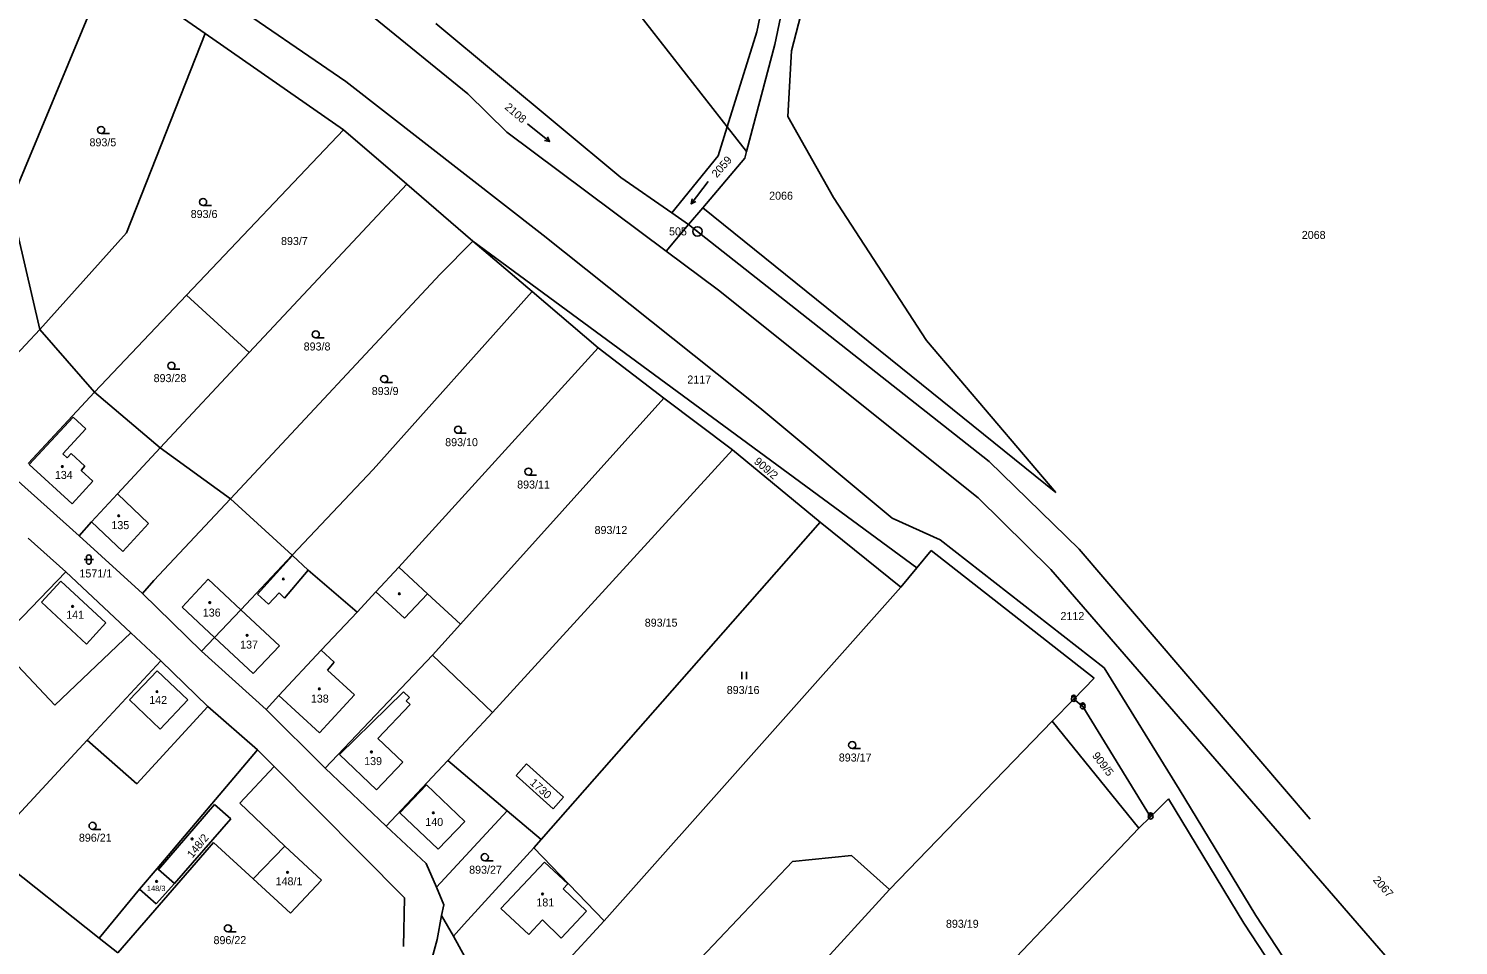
# Model space of a CAD drawing. Extents: x -801826 to -800592, y -1032871 to -1031813.
# Drawn here: x -800902.2 to -800598.5, y -1032747.9 to -1032553.2 of the extents above; entities that cross this region are included whole.
import ezdxf

# ---------------------------------------------------------------- set-up
doc = ezdxf.new("R2010")
doc.units = 0
for name, color, linetype in [('Vrstva 1', 7, 'Continuous'), ('Vrstva 17', 7, 'Continuous'), ('Vrstva 18', 7, 'Continuous'), ('Vrstva 19', 7, 'Continuous'), ('Vrstva 24', 7, 'Continuous'), ('Vrstva 25', 7, 'Continuous'), ('Vrstva 4', 7, 'Continuous')]:
    doc.layers.add(name, color=color, linetype=linetype)

msp = doc.modelspace()

# ---------------------------------------------------------------- linework, layer by layer
at = {"layer": 'Vrstva 1'}
for p, q in [((-800747.51, -1032553.85), (-800720.4, -1032423.37)), ((-800743.69, -1032556.55), (-800734.56, -1032513.71)), ((-800795.04, -1032521.25), (-800753.78, -1032574.05)), ((-800740.12, -1032557.88), (-800734.46, -1032535.8)), ((-800906.01, -1032590.17), (-800885.17, -1032539.97)), ((-800884.24, -1032540.59), (-800864.66, -1032554.23)), ((-800834.81, -1032564.44), (-800862.95, -1032545.07)), ((-800828.93, -1032550.72), (-800808.91, -1032567.02)), ((-800815.65, -1032552.08), (-800776.4, -1032584.81)), ((-800881.38, -1032596.58), (-800864.66, -1032554.23)), ((-800864.66, -1032554.23), (-800835.29, -1032574.68)), ((-800753.78, -1032574.05), (-800747.51, -1032553.85)), ((-800749.69, -1032579.25), (-800743.69, -1032556.55)), ((-800740.88, -1032571.84), (-800740.12, -1032557.88)), ((-800792.86, -1032597.07), (-800834.81, -1032564.44)), ((-800808.91, -1032567.02), (-800800.57, -1032575.14)), ((-800755.69, -1032580.22), (-800753.78, -1032574.05)), ((-800753.78, -1032574.05), (-800749.69, -1032579.25)), ((-800731.22, -1032589.07), (-800740.88, -1032571.84)), ((-800868.63, -1032609.77), (-800835.29, -1032574.68)), ((-800821.82, -1032586.21), (-800835.29, -1032574.68)), ((-800766.77, -1032600.41), (-800800.57, -1032575.14)), ((-800765.55, -1032592.3), (-800755.69, -1032580.22)), ((-800750.07, -1032580.68), (-800749.69, -1032579.25)), ((-800758.99, -1032591.22), (-800750.07, -1032580.68)), ((-800855.31, -1032621.97), (-800821.82, -1032586.21)), ((-800807.81, -1032598.33), (-800821.82, -1032586.21)), ((-800776.4, -1032584.81), (-800765.55, -1032592.3)), ((-800711.46, -1032619.4), (-800731.22, -1032589.07)), ((-800899.82, -1032617.08), (-800906.01, -1032590.17)), ((-800765.55, -1032592.3), (-800761.99, -1032594.76)), ((-800761.99, -1032594.76), (-800758.99, -1032591.22)), ((-800758.99, -1032591.22), (-800684, -1032651.66)), ((-800761.99, -1032594.76), (-800766.77, -1032600.41)), ((-800698.17, -1032645.09), (-800761.99, -1032594.76)), ((-800899.82, -1032617.08), (-800881.38, -1032596.58)), ((-800814.78, -1032605.32), (-800807.81, -1032598.33)), ((-800713.51, -1032667.66), (-800807.81, -1032598.33)), ((-800795.21, -1032609.02), (-800807.81, -1032598.33)), ((-800746.85, -1032633.68), (-800792.86, -1032597.07)), ((-800755.66, -1032608.71), (-800766.77, -1032600.41)), ((-800859.27, -1032653.03), (-800814.78, -1032605.32)), ((-800888.19, -1032630.36), (-800868.63, -1032609.77)), ((-800868.63, -1032609.77), (-800855.31, -1032621.97)), ((-800829.01, -1032646.84), (-800795.21, -1032609.02)), ((-800781.17, -1032620.96), (-800795.21, -1032609.02)), ((-800755.66, -1032608.71), (-800700.48, -1032652.79)), ((-800899.82, -1032617.08), (-800910.98, -1032628.99)), ((-800888.19, -1032630.36), (-800899.82, -1032617.08)), ((-800684, -1032651.66), (-800711.46, -1032619.4)), ((-800874.26, -1032642.21), (-800855.31, -1032621.97)), ((-800823.54, -1032667.55), (-800781.17, -1032620.96)), ((-800781.17, -1032620.96), (-800767.24, -1032631.65)), ((-800902.29, -1032645.52), (-800888.19, -1032630.36)), ((-800874.26, -1032642.21), (-800888.19, -1032630.36)), ((-800810.46, -1032679.66), (-800767.24, -1032631.65)), ((-800767.24, -1032631.65), (-800752.63, -1032642.64)), ((-800718.76, -1032657.14), (-800746.85, -1032633.68)), ((-800883.28, -1032651.94), (-800874.26, -1032642.21)), ((-800874.26, -1032642.21), (-800859.27, -1032653.03)), ((-800752.63, -1032642.64), (-800803.67, -1032698.44)), ((-800734.01, -1032657.96), (-800752.63, -1032642.64)), ((-800846.17, -1032664.97), (-800829.01, -1032646.84)), ((-800679.03, -1032663.74), (-800698.17, -1032645.09)), ((-800891.41, -1032660.9), (-800905.05, -1032648.69)), ((-800888.84, -1032657.94), (-800883.28, -1032651.94)), ((-800875.6, -1032670.39), (-800859.27, -1032653.03)), ((-800846.17, -1032664.97), (-800859.27, -1032653.03)), ((-800700.48, -1032652.79), (-800685.05, -1032668.07)), ((-800891.41, -1032660.9), (-800888.84, -1032657.94)), ((-800793.3, -1032725.41), (-800734.01, -1032657.96)), ((-800734.01, -1032657.96), (-800716.93, -1032671.82)), ((-800708.57, -1032661.74), (-800718.76, -1032657.14)), ((-800894.26, -1032668.56), (-800902.29, -1032661.37)), ((-800877.98, -1032673.15), (-800891.41, -1032660.9)), ((-800673.72, -1032688.93), (-800708.57, -1032661.74)), ((-800857.07, -1032676.61), (-800846.17, -1032664.97)), ((-800846.09, -1032665.04), (-800846.17, -1032664.97)), ((-800842.77, -1032668.15), (-800846.09, -1032665.04)), ((-800710.49, -1032664.04), (-800713.51, -1032667.66)), ((-800675.83, -1032691.09), (-800710.49, -1032664.04)), ((-800629.94, -1032721.03), (-800679.03, -1032663.74)), ((-800908.97, -1032683.75), (-800894.26, -1032668.56)), ((-800880.44, -1032681.5), (-800894.26, -1032668.56)), ((-800832.41, -1032677.07), (-800842.77, -1032668.15)), ((-800828.41, -1032672.79), (-800823.54, -1032667.55)), ((-800823.54, -1032667.55), (-800817.45, -1032673.19)), ((-800713.51, -1032667.66), (-800716.93, -1032671.82)), ((-800685.05, -1032668.07), (-800610.32, -1032754.24)), ((-800877.98, -1032673.15), (-800875.6, -1032670.39)), ((-800865.46, -1032685.41), (-800877.98, -1032673.15)), ((-800832.41, -1032677.07), (-800828.41, -1032672.79)), ((-800817.45, -1032673.19), (-800810.46, -1032679.66)), ((-800716.93, -1032671.82), (-800779.9, -1032742.67)), ((-800862.68, -1032682.47), (-800857.07, -1032676.61)), ((-800840.04, -1032685.14), (-800832.41, -1032677.07)), ((-800816.36, -1032686.22), (-800810.46, -1032679.66)), ((-800908.97, -1032683.75), (-800896.63, -1032696.82)), ((-800896.63, -1032696.82), (-800880.44, -1032681.5)), ((-800874.12, -1032687.42), (-800880.44, -1032681.5)), ((-800865.46, -1032685.41), (-800862.68, -1032682.47)), ((-800851.7, -1032697.76), (-800865.46, -1032685.41)), ((-800849.02, -1032694.81), (-800840.04, -1032685.14)), ((-800839.18, -1032710.22), (-800816.36, -1032686.22)), ((-800816.36, -1032686.22), (-800803.67, -1032698.44)), ((-800889.71, -1032704.26), (-800874.12, -1032687.42)), ((-800864.1, -1032697.13), (-800874.12, -1032687.42)), ((-800657.77, -1032714.7), (-800673.72, -1032688.93)), ((-800680.18, -1032695.55), (-800675.83, -1032691.09)), ((-800851.7, -1032697.76), (-800849.02, -1032694.81)), ((-800684.75, -1032700.23), (-800680.18, -1032695.55)), ((-800678.26, -1032697.15), (-800680.18, -1032695.55)), ((-800864.1, -1032697.13), (-800879.2, -1032713.56)), ((-800853.56, -1032706.35), (-800864.1, -1032697.13)), ((-800839.18, -1032710.22), (-800851.7, -1032697.76)), ((-800803.67, -1032698.44), (-800813.1, -1032708.63)), ((-800663.84, -1032720.54), (-800678.26, -1032697.15)), ((-800719.34, -1032735.97), (-800684.75, -1032700.23)), ((-800666.33, -1032723), (-800684.75, -1032700.23)), ((-800911.15, -1032727.37), (-800889.71, -1032704.26)), ((-800879.2, -1032713.56), (-800889.71, -1032704.26)), ((-800874.85, -1032731.51), (-800853.56, -1032706.35)), ((-800850.03, -1032709.9), (-800853.56, -1032706.35)), ((-800857.32, -1032717.69), (-800850.03, -1032709.9)), ((-800850.03, -1032709.9), (-800822.34, -1032737.75)), ((-800826.26, -1032722.56), (-800839.18, -1032710.22)), ((-800813.1, -1032708.63), (-800826.26, -1032722.56)), ((-800813.1, -1032708.63), (-800800.53, -1032719.29)), ((-800798.61, -1032711.8), (-800796.41, -1032709.34)), ((-800796.41, -1032709.34), (-800788.55, -1032716.38)), ((-800790.75, -1032718.84), (-800798.61, -1032711.8)), ((-800788.55, -1032716.38), (-800790.75, -1032718.84)), ((-800660.02, -1032716.77), (-800663.84, -1032720.54)), ((-800644.04, -1032743.12), (-800660.02, -1032716.77)), ((-800641.5, -1032741.52), (-800657.77, -1032714.7)), ((-800874.61, -1032731.74), (-800862.71, -1032717.98)), ((-800862.71, -1032717.98), (-800859.24, -1032721.02)), ((-800847.74, -1032726.79), (-800857.32, -1032717.69)), ((-800800.53, -1032719.29), (-800815.57, -1032735.5)), ((-800800.53, -1032719.29), (-800793.3, -1032725.41)), ((-800859.24, -1032721.02), (-800871.19, -1032734.75)), ((-800826.26, -1032722.56), (-800817.71, -1032730.51)), ((-800704.52, -1032763.01), (-800666.33, -1032723)), ((-800666.33, -1032723), (-800663.84, -1032720.54)), ((-800862.89, -1032726), (-800883.21, -1032749.46)), ((-800854.49, -1032733.72), (-800862.89, -1032726)), ((-800794.87, -1032727.17), (-800793.3, -1032725.41)), ((-800887.16, -1032746.32), (-800911.15, -1032727.37)), ((-800839.99, -1032734.05), (-800847.74, -1032726.79)), ((-800794.87, -1032727.17), (-800809.66, -1032743.38)), ((-800794.87, -1032727.17), (-800779.9, -1032742.67)), ((-800727.36, -1032728.75), (-800739.93, -1032730.06)), ((-800719.34, -1032735.97), (-800727.36, -1032728.75)), ((-800878.59, -1032735.91), (-800874.85, -1032731.51)), ((-800874.85, -1032731.51), (-800874.61, -1032731.74)), ((-800874.61, -1032731.74), (-800871.19, -1032734.75)), ((-800817.71, -1032730.51), (-800815.57, -1032735.5)), ((-800792.6, -1032730.18), (-800801.86, -1032740.03)), ((-800787.64, -1032734.82), (-800792.6, -1032730.18)), ((-800775.49, -1032767.53), (-800739.93, -1032730.06)), ((-800871.19, -1032734.75), (-800875.08, -1032739.04)), ((-800846.53, -1032741.02), (-800854.49, -1032733.72)), ((-800846.53, -1032741.02), (-800839.99, -1032734.05)), ((-800788.6, -1032735.85), (-800787.64, -1032734.82)), ((-800887.16, -1032746.32), (-800878.59, -1032735.91)), ((-800875.08, -1032739.04), (-800878.59, -1032735.91)), ((-800822.52, -1032748.12), (-800822.34, -1032737.75)), ((-800815.57, -1032735.5), (-800813.95, -1032739.28)), ((-800783.65, -1032740.59), (-800788.6, -1032735.85)), ((-800719.34, -1032735.97), (-800755.52, -1032775.59)), ((-800815.39, -1032746.59), (-800814.46, -1032741.51)), ((-800813.95, -1032739.28), (-800814.46, -1032741.51)), ((-800814.46, -1032741.51), (-800811.93, -1032745.91)), ((-800801.86, -1032740.03), (-800795.94, -1032745.59)), ((-800789.09, -1032746.32), (-800783.65, -1032740.59)), ((-800598.47, -1032807.13), (-800641.5, -1032741.52)), ((-800811.93, -1032745.91), (-800809.66, -1032743.38)), ((-800795.94, -1032745.59), (-800793.01, -1032742.47)), ((-800793.01, -1032742.47), (-800789.09, -1032746.32)), ((-800779.9, -1032742.67), (-800788.9, -1032752.39)), ((-800600.58, -1032809.38), (-800644.04, -1032743.12)), ((-800883.21, -1032749.46), (-800887.16, -1032746.32)), ((-800816.49, -1032750.53), (-800815.39, -1032746.59)), ((-800801.15, -1032765.61), (-800811.93, -1032745.91))]:
    msp.add_line(p, q, dxfattribs=at)
at = {"layer": 'Vrstva 24'}
for centre, radius in [((-800760.12, -1032596.24), 1), ((-800760.12, -1032596.24), 0.0439), ((-800680.18, -1032695.55), 0.5), ((-800680.18, -1032695.55), 0.0364), ((-800678.26, -1032697.15), 0.5), ((-800678.26, -1032697.15), 0.0364), ((-800663.84, -1032720.54), 0.5), ((-800663.84, -1032720.54), 0.0364)]:
    msp.add_circle(centre, radius, dxfattribs=at)
for centre in [(-800680.18, -1032695.18), (-800678.26, -1032696.78), (-800663.84, -1032720.17)]:
    msp.add_arc(centre, 0.45, 344.4473, 196.3778, dxfattribs=at)
at = {"layer": 'Vrstva 25'}
for p, q in [((-800796.19, -1032573.38), (-800791.53, -1032577.14)), ((-800885.03, -1032575.44), (-800886.78, -1032575.44)), ((-800757.81, -1032585.63), (-800761.43, -1032590.41)), ((-800863.36, -1032590.75), (-800865.11, -1032590.75)), ((-800839.43, -1032618.86), (-800841.18, -1032618.86)), ((-800870.09, -1032625.53), (-800871.84, -1032625.53)), ((-800824.9, -1032628.35), (-800826.65, -1032628.35)), ((-800809.21, -1032639.12), (-800810.96, -1032639.12)), ((-800794.27, -1032648), (-800796.02, -1032648)), ((-800889.9, -1032666.43), (-800889.9, -1032665.43)), ((-800888.9, -1032666.43), (-800888.9, -1032665.43)), ((-800890.4, -1032665.93), (-800888.4, -1032665.93)), ((-800750.71, -1032689.8), (-800750.71, -1032691.3)), ((-800749.69, -1032691.3), (-800749.69, -1032689.8)), ((-800725.49, -1032706.08), (-800727.24, -1032706.08)), ((-800886.84, -1032723.23), (-800888.59, -1032723.23)), ((-800803.52, -1032729.89), (-800805.27, -1032729.89)), ((-800858.1, -1032744.99), (-800859.85, -1032744.99))]:
    msp.add_line(p, q, dxfattribs=at)
for points in [[(-800791.99, -1032576.13), (-800791.53, -1032577.14), (-800792.62, -1032576.91)], [(-800760.43, -1032589.92), (-800761.43, -1032590.41), (-800761.23, -1032589.31)]]:
    msp.add_lwpolyline(points, dxfattribs=at)
for centre, radius in [((-800886.78, -1032574.69), 0.75), ((-800865.11, -1032590), 0.75), ((-800841.18, -1032618.11), 0.75), ((-800871.84, -1032624.78), 0.75), ((-800826.65, -1032627.6), 0.75), ((-800810.96, -1032638.37), 0.75), ((-800895.01, -1032646.18), 0.175), ((-800796.02, -1032647.25), 0.75), ((-800883.03, -1032656.64), 0.175), ((-800848.07, -1032670.05), 0.175), ((-800823.43, -1032673.2), 0.175), ((-800892.85, -1032675.89), 0.175), ((-800863.7, -1032675.06), 0.175), ((-800855.76, -1032682.03), 0.175), ((-800874.91, -1032693.97), 0.175), ((-800840.41, -1032693.39), 0.175), ((-800727.24, -1032705.33), 0.75), ((-800829.36, -1032706.77), 0.175), ((-800816.22, -1032719.72), 0.175), ((-800888.59, -1032722.48), 0.75), ((-800867.44, -1032725.25), 0.175), ((-800805.27, -1032729.14), 0.75), ((-800847.18, -1032732.37), 0.175), ((-800875, -1032734.3), 0.175), ((-800793.01, -1032736.96), 0.175), ((-800859.85, -1032744.24), 0.75)]:
    msp.add_circle(centre, radius, dxfattribs=at)
for centre, start, end in [((-800889.4, -1032665.43), 0, 180), ((-800889.4, -1032666.43), 180, 0)]:
    msp.add_arc(centre, 0.5, start, end, dxfattribs=at)
at = {"layer": 'Vrstva 4'}
for p, q in [((-800892.74, -1032635.69), (-800902.07, -1032645.72)), ((-800894.88, -1032643.5), (-800890.01, -1032638.19)), ((-800890.01, -1032638.19), (-800892.74, -1032635.69)), ((-800893.99, -1032644.31), (-800894.88, -1032643.5)), ((-800893.15, -1032643.39), (-800893.99, -1032644.31)), ((-800890.2, -1032646.09), (-800893.15, -1032643.39)), ((-800892.93, -1032654.1), (-800902.07, -1032645.72)), ((-800891.04, -1032647.01), (-800890.2, -1032646.09)), ((-800888.54, -1032649.31), (-800891.04, -1032647.01)), ((-800892.93, -1032654.1), (-800888.54, -1032649.31)), ((-800876.72, -1032658.25), (-800883.28, -1032651.94)), ((-800888.84, -1032657.94), (-800882.19, -1032664.22)), ((-800882.19, -1032664.22), (-800876.72, -1032658.25)), ((-800846.09, -1032665.04), (-800853.54, -1032673.28)), ((-800847.81, -1032674.11), (-800842.77, -1032668.15)), ((-800899.47, -1032674.98), (-800895.31, -1032670.5)), ((-800895.31, -1032670.5), (-800885.74, -1032679.39)), ((-800864.01, -1032670.11), (-800869.56, -1032676.04)), ((-800857.07, -1032676.61), (-800864.01, -1032670.11)), ((-800853.54, -1032673.28), (-800851.24, -1032675.43)), ((-800851.24, -1032675.43), (-800848.98, -1032673.02)), ((-800848.98, -1032673.02), (-800847.81, -1032674.11)), ((-800822.32, -1032678.36), (-800828.41, -1032672.79)), ((-800817.45, -1032673.19), (-800822.32, -1032678.36)), ((-800889.86, -1032683.9), (-800899.47, -1032674.98)), ((-800862.68, -1032682.47), (-800869.56, -1032676.04)), ((-800857.07, -1032676.61), (-800848.92, -1032684.23)), ((-800885.74, -1032679.39), (-800889.86, -1032683.9)), ((-800854.47, -1032690.16), (-800862.68, -1032682.47)), ((-800848.92, -1032684.23), (-800854.47, -1032690.16)), ((-800837.26, -1032687.72), (-800840.04, -1032685.14)), ((-800880.77, -1032695.75), (-800874.88, -1032689.53)), ((-800874.88, -1032689.53), (-800868.33, -1032695.73)), ((-800838.67, -1032689.39), (-800837.26, -1032687.72)), ((-800832.92, -1032694.67), (-800838.67, -1032689.39)), ((-800874.22, -1032701.95), (-800880.77, -1032695.75)), ((-800868.33, -1032695.73), (-800874.22, -1032701.95)), ((-800840.37, -1032702.76), (-800849.02, -1032694.81)), ((-800840.37, -1032702.76), (-800832.92, -1032694.67)), ((-800822.56, -1032693.99), (-800836.14, -1032707.35)), ((-800821.27, -1032695.22), (-800822.56, -1032693.99)), ((-800821.95, -1032695.94), (-800821.27, -1032695.22)), ((-800821.12, -1032696.73), (-800821.95, -1032695.94)), ((-800827.97, -1032703.94), (-800821.12, -1032696.73)), ((-800822.7, -1032708.93), (-800827.97, -1032703.94)), ((-800836.14, -1032707.35), (-800828.28, -1032714.81)), ((-800828.28, -1032714.81), (-800822.7, -1032708.93)), ((-800817.63, -1032713.78), (-800823.29, -1032719.72)), ((-800809.51, -1032721.53), (-800817.63, -1032713.78)), ((-800823.29, -1032719.72), (-800815.17, -1032727.47)), ((-800815.17, -1032727.47), (-800809.51, -1032721.53)), ((-800854.49, -1032733.72), (-800847.74, -1032726.79))]:
    msp.add_line(p, q, dxfattribs=at)

# ---------------------------------------------------------------- texts
at = {"layer": 'Vrstva 17'}
msp.add_text('505', height=1.7, dxfattribs=at).set_placement((-800766.14, -1032597.09))
at = {"layer": 'Vrstva 18'}
for s, rotation, p in [('2108', 319.4813, (-800801.19, -1032570.08)), ('2059', 48.6441, (-800755.98, -1032584.96)), ('909/2', 319.6741, (-800748.24, -1032645.35)), ('909/5', 307.5242, (-800676.37, -1032707.6)), ('1730', 318.4028, (-800795.83, -1032713.54)), ('2067', 310.9442, (-800616.73, -1032734.04))]:
    msp.add_text(s, height=1.7, rotation=rotation, dxfattribs=at).set_placement(p)
for s, p in [('893/5', (-800889.24, -1032578.17)), ('2066', (-800744.88, -1032589.51)), ('893/6', (-800867.75, -1032593.39)), ('893/7', (-800848.56, -1032599.13)), ('2068', (-800631.74, -1032597.84)), ('893/8', (-800843.75, -1032621.53)), ('893/28', (-800875.62, -1032628.25)), ('2117', (-800762.26, -1032628.55)), ('893/9', (-800829.29, -1032630.99)), ('893/10', (-800813.69, -1032641.85)), ('893/11', (-800798.4, -1032650.85)), ('893/12', (-800781.96, -1032660.51)), ('1571/1', (-800891.38, -1032669.73)), ('2112', (-800682.99, -1032678.78)), ('893/15', (-800771.3, -1032680.18)), ('893/16', (-800753.88, -1032694.48)), ('893/17', (-800730.08, -1032708.82)), ('896/21', (-800891.49, -1032725.85)), ('893/27', (-800808.6, -1032732.65)), ('893/19', (-800707.32, -1032744.13)), ('896/22', (-800862.9, -1032747.6))]:
    msp.add_text(s, height=1.7, dxfattribs=at).set_placement(p)
at = {"layer": 'Vrstva 19'}
for s, height, p in [('134', 1.7, (-800896.6, -1032648.81)), ('135', 1.7, (-800884.59, -1032659.47)), ('141', 1.7, (-800894.19, -1032678.51)), ('136', 1.7, (-800865.18, -1032678.04)), ('137', 1.7, (-800857.25, -1032684.84)), ('142', 1.7, (-800876.56, -1032696.61)), ('138', 1.7, (-800842.22, -1032696.31)), ('139', 1.7, (-800830.9, -1032709.58)), ('140', 1.7, (-800817.91, -1032722.5)), ('148/3', 1.14, (-800877.05, -1032736.34)), ('148/1', 1.7, (-800849.71, -1032735.11)), ('181', 1.7, (-800794.32, -1032739.6))]:
    msp.add_text(s, height=height, dxfattribs=at).set_placement(p)
msp.add_text('148/2', height=1.7, rotation=50.7391, dxfattribs=at).set_placement((-800867.4, -1032729.47))

doc.saveas('drawing.dxf')
